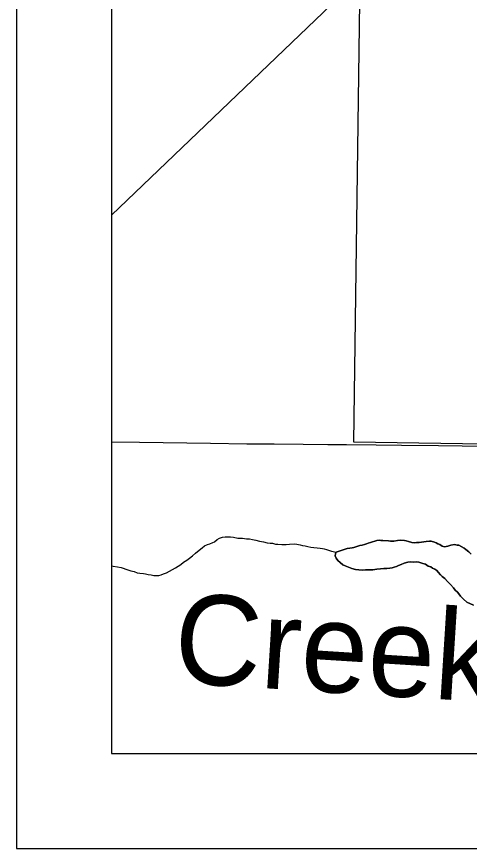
# Model space of a CAD drawing. Extents: x 0 to 34, y 0 to 22.
# Drawn here: x 2 to 2.477, y 14 to 14.876 of the extents above; entities that cross this region are included whole.
import ezdxf

# ---------------------------------------------------------------- set-up
doc = ezdxf.new("R2010")
doc.units = 0
for name, color, linetype in [('GM_X_Minor_Lake', 7, 'Continuous'), ('GM_X_Minor_River', 7, 'Continuous'), ('GM_X_Minor_River_Text', 7, 'Continuous'), ('GM_X_Section', 7, 'Continuous'), ('GM_X_Township_Road', 7, 'Continuous'), ('SH_Data', 7, 'Continuous')]:
    doc.layers.add(name, color=color, linetype=linetype)

msp = doc.modelspace()

# ---------------------------------------------------------------- linework, layer by layer
at = {"layer": 'GM_X_Minor_Lake'}
for points in [[(2.47879, 14.30977), (2.4762, 14.31214), (2.47324, 14.3149), (2.47137, 14.3161), (2.46576, 14.31933), (2.46386, 14.31939), (2.46121, 14.31986), (2.45738, 14.31923), (2.4543, 14.31819), (2.45047, 14.31756), (2.44821, 14.31839), (2.4456, 14.32), (2.44372, 14.32083), (2.44184, 14.32165), (2.43997, 14.32247), (2.43657, 14.32335), (2.43467, 14.32341), (2.43123, 14.32315), (2.42893, 14.32284), (2.42626, 14.32255), (2.42396, 14.32224), (2.42129, 14.32195), (2.41861, 14.32166), (2.41634, 14.32212), (2.41256, 14.32301), (2.4103, 14.32384), (2.40842, 14.32428), (2.40461, 14.32441), (2.40118, 14.32415), (2.39735, 14.32351), (2.39392, 14.32363), (2.39164, 14.3237), (2.38556, 14.32429), (2.38366, 14.32435), (2.38176, 14.32441), (2.37946, 14.32411), (2.37716, 14.32342), (2.37485, 14.32274), (2.37254, 14.32206), (2.37024, 14.32137), (2.36831, 14.32068), (2.36638, 14.31998), (2.36408, 14.3193), (2.3614, 14.319), (2.35948, 14.31831), (2.35717, 14.31762), (2.35524, 14.31693), (2.35333, 14.31661), (2.35103, 14.31631), (2.34796, 14.31565), (2.33642, 14.31185)], [(2.33642, 14.31185), (2.34796, 14.31565), (2.35103, 14.31631), (2.35333, 14.31661), (2.35524, 14.31693), (2.35717, 14.31762), (2.35948, 14.31831), (2.3614, 14.319), (2.36408, 14.3193), (2.36638, 14.31998), (2.36831, 14.32068), (2.37024, 14.32137), (2.37254, 14.32206), (2.37485, 14.32274), (2.37716, 14.32342), (2.37946, 14.32411), (2.38176, 14.32441), (2.38366, 14.32435), (2.38556, 14.32429), (2.39164, 14.3237), (2.39392, 14.32363), (2.39735, 14.32351), (2.40118, 14.32415), (2.40461, 14.32441), (2.40842, 14.32428), (2.4103, 14.32384), (2.41256, 14.32301), (2.41634, 14.32212), (2.41861, 14.32166), (2.42129, 14.32195), (2.42396, 14.32224), (2.42626, 14.32255), (2.42893, 14.32284), (2.43123, 14.32315), (2.43467, 14.32341), (2.43657, 14.32335), (2.43997, 14.32247), (2.44184, 14.32165), (2.44372, 14.32083), (2.4456, 14.32), (2.44821, 14.31839), (2.45047, 14.31756), (2.4543, 14.31819), (2.45738, 14.31923), (2.46121, 14.31986), (2.46386, 14.31939), (2.46576, 14.31933), (2.47137, 14.3161), (2.47324, 14.3149), (2.4762, 14.31214), (2.47879, 14.30977)], [(2.33642, 14.31185), (2.33599, 14.31034), (2.33553, 14.30807), (2.3366, 14.30575), (2.33842, 14.30303), (2.34064, 14.30105), (2.34361, 14.29867), (2.34586, 14.29746), (2.353, 14.29456), (2.35678, 14.29367), (2.36058, 14.29316), (2.364, 14.29305), (2.36744, 14.29331), (2.37048, 14.29321), (2.37506, 14.29344), (2.37927, 14.29406), (2.38308, 14.29431), (2.3869, 14.29457), (2.38996, 14.29484), (2.39301, 14.29512), (2.39569, 14.29541), (2.39761, 14.29611), (2.39992, 14.2968), (2.40224, 14.29786), (2.40494, 14.29891), (2.40803, 14.30033), (2.41187, 14.30134)], [(2.41187, 14.30134), (2.40803, 14.30033), (2.40494, 14.29891), (2.40224, 14.29786), (2.39992, 14.2968), (2.39761, 14.29611), (2.39569, 14.29541), (2.39301, 14.29512), (2.38996, 14.29484), (2.3869, 14.29457), (2.38308, 14.29431), (2.37927, 14.29406), (2.37506, 14.29344), (2.37048, 14.29321), (2.36744, 14.29331), (2.364, 14.29305), (2.36058, 14.29316), (2.35678, 14.29367), (2.353, 14.29456), (2.34586, 14.29746), (2.34361, 14.29867), (2.34064, 14.30105), (2.33842, 14.30303), (2.3366, 14.30575), (2.33553, 14.30807), (2.33599, 14.31034), (2.33642, 14.31185)], [(2.41187, 14.30134), (2.41493, 14.30162), (2.41797, 14.30152), (2.42102, 14.3018), (2.42368, 14.30133), (2.42782, 14.30005), (2.43046, 14.2992), (2.43345, 14.2972), (2.43609, 14.29635), (2.43795, 14.29515), (2.44058, 14.29392), (2.44244, 14.29271), (2.4439, 14.29076), (2.44648, 14.28802), (2.44834, 14.28643), (2.45093, 14.28406), (2.45387, 14.28092), (2.45682, 14.27778), (2.46013, 14.27424), (2.46196, 14.2719), (2.46418, 14.26993), (2.46564, 14.26797), (2.46748, 14.26563), (2.4708, 14.26248), (2.47413, 14.25932), (2.48126, 14.25604)], [(2.48126, 14.25604), (2.47413, 14.25932), (2.4708, 14.26248), (2.46748, 14.26563), (2.46564, 14.26797), (2.46418, 14.26993), (2.46196, 14.2719), (2.46013, 14.27424), (2.45682, 14.27778), (2.45387, 14.28092), (2.45093, 14.28406), (2.44834, 14.28643), (2.44648, 14.28802), (2.4439, 14.29076), (2.44244, 14.29271), (2.44058, 14.29392), (2.43795, 14.29515), (2.43609, 14.29635), (2.43345, 14.2972), (2.43046, 14.2992), (2.42782, 14.30005), (2.42368, 14.30133), (2.42102, 14.3018), (2.41797, 14.30152), (2.41493, 14.30162), (2.41187, 14.30134)]]:
    msp.add_lwpolyline(points, dxfattribs=at)
at = {"layer": 'GM_X_Minor_River'}
msp.add_line((2.1, 14.66697), (3.7075, 16.20645), dxfattribs=at)
for points in [[(2.1, 14.29754), (2.10173, 14.29722), (2.10627, 14.29631), (2.11007, 14.2958), (2.11232, 14.29496), (2.11496, 14.29411), (2.11722, 14.29328), (2.12024, 14.29241), (2.12364, 14.29154), (2.12703, 14.29029), (2.12968, 14.28982), (2.13347, 14.28931), (2.13575, 14.28924), (2.13839, 14.28839), (2.1418, 14.28789), (2.14446, 14.28742), (2.14674, 14.28735), (2.14978, 14.28725), (2.15209, 14.28793), (2.15479, 14.28898), (2.15787, 14.29002), (2.16718, 14.29542), (2.17028, 14.29722), (2.17301, 14.29903), (2.17574, 14.30122), (2.17924, 14.30339), (2.18198, 14.30558), (2.1851, 14.30814), (2.18823, 14.3107), (2.19215, 14.31399), (2.19528, 14.31655), (2.19801, 14.31874), (2.2011, 14.32016), (2.20341, 14.32084), (2.2065, 14.32226), (2.20843, 14.32296), (2.21117, 14.32515), (2.2135, 14.32659), (2.21696, 14.32762), (2.21963, 14.32791), (2.22231, 14.3282), (2.22535, 14.3281), (2.22838, 14.32762), (2.23292, 14.32671), (2.23787, 14.32654), (2.24204, 14.32602), (2.24509, 14.32592), (2.2485, 14.32543), (2.2519, 14.32456), (2.25568, 14.32367), (2.25984, 14.32277), (2.264, 14.32187), (2.26703, 14.32139), (2.26931, 14.32131)], [(2.26931, 14.32131), (2.27271, 14.32044), (2.275, 14.32036), (2.27917, 14.31984), (2.28374, 14.32007), (2.28756, 14.32032), (2.29214, 14.32055), (2.29518, 14.32045), (2.29858, 14.31958), (2.30123, 14.31911), (2.30388, 14.31864), (2.30652, 14.31779), (2.30993, 14.3173), (2.3198, 14.3162), (2.32207, 14.31575), (2.32396, 14.31531), (2.32623, 14.31485), (2.32849, 14.31401), (2.33151, 14.31315), (2.33642, 14.31185)]]:
    msp.add_lwpolyline(points, dxfattribs=at)
at = {"layer": 'GM_X_Section'}
msp.add_lwpolyline([(2.36882, 15.43324), (3.35868, 15.41381), (3.33901, 14.41257), (2.35513, 14.42769)], close=True, dxfattribs=at)
at = {"layer": 'GM_X_Township_Road'}
for points in [[(2.1, 18.40743), (2.1, 14.1), (7.35068, 14.1), (7.35419, 14.31073), (7.37669, 15.31551), (7.38543, 16.36959)], [(2.1, 14.42816), (2.12945, 14.4277), (2.20404, 14.42668), (2.24258, 14.42613), (2.27117, 14.4259), (2.30164, 14.42567), (2.32765, 14.42543), (2.34727, 14.42526), (2.37872, 14.4251), (2.40528, 14.42476), (2.44423, 14.42432), (2.4694, 14.42397), (2.51787, 14.42297), (2.53155, 14.42272), (2.58216, 14.42238)]]:
    msp.add_lwpolyline(points, dxfattribs=at)
at = {"layer": 'SH_Data'}
for p, q in [((2, 21), (2, 14)), ((2.1, 20.9), (2.1, 14.1)), ((2.1, 14.1), (8.9, 14.1)), ((2.1, 14.1), (2.1, 14.1)), ((2, 14), (9, 14))]:
    msp.add_line(p, q, dxfattribs=at)

# ---------------------------------------------------------------- texts
at = {"layer": 'GM_X_Minor_River_Text'}
msp.add_text('Creek', height=0.094743, rotation=356.41895, dxfattribs=at).set_placement((2.16391, 14.17474))

doc.saveas('drawing.dxf')
